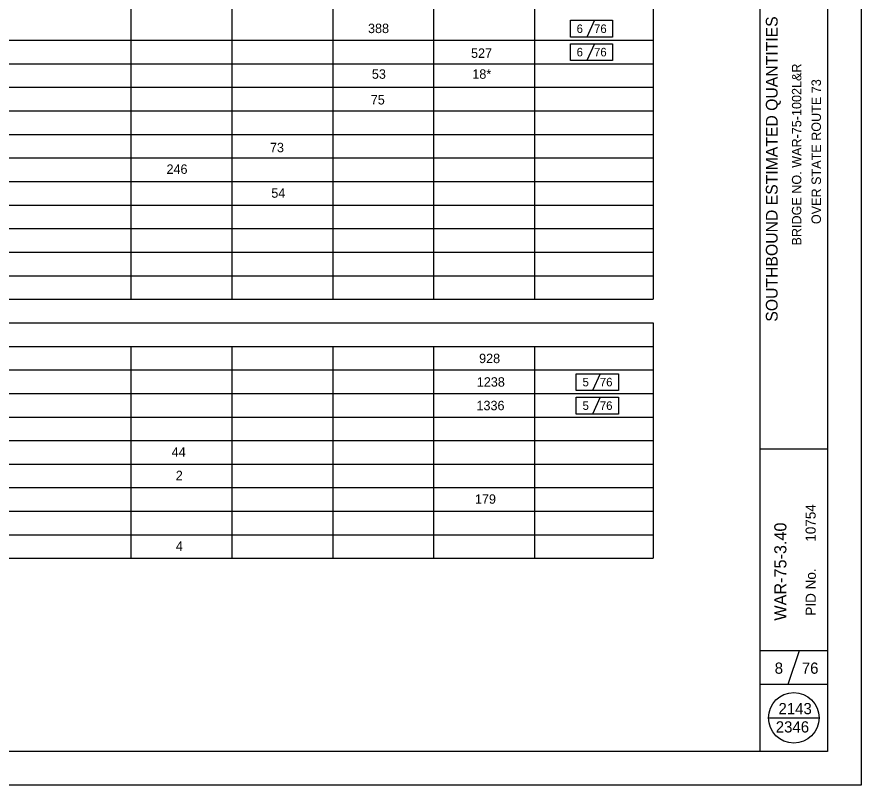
# Model space of a CAD drawing. Extents: x 0 to 34, y 0 to 22.
# Drawn here: x 21.46 to 34, y 0 to 11.42 of the extents above; entities that cross this region are included whole.
import ezdxf

# ---------------------------------------------------------------- set-up
doc = ezdxf.new("R2010")
doc.units = 0
for name, color, linetype in [('BR_P_Gen_Text', 7, 'Continuous'), ('BR_P_Sub_Text', 7, 'Continuous'), ('SH_Border', 7, 'Continuous'), ('SH_Cut_Line', 7, 'Continuous'), ('SH_Data', 7, 'Continuous'), ('SH_Text', 7, 'Continuous')]:
    doc.layers.add(name, color=color, linetype=linetype)

msp = doc.modelspace()

# ---------------------------------------------------------------- linework, layer by layer
at = {"layer": 'BR_P_Gen_Text'}
for p, q in [((30.038, 11.367), (29.923, 11.117)), ((30.038, 11.019), (29.923, 10.769)), ((30.125, 6.115), (30.009, 5.865)), ((30.125, 5.765), (30.009, 5.515))]:
    msp.add_line(p, q, dxfattribs=at)
for points in [[(29.681, 11.367), (30.307, 11.367), (30.307, 11.117), (29.681, 11.117)], [(29.681, 11.367), (30.307, 11.367), (30.307, 11.117), (29.681, 11.117)], [(29.681, 11.019), (30.307, 11.019), (30.307, 10.769), (29.681, 10.769)], [(29.681, 11.019), (30.307, 11.019), (30.307, 10.769), (29.681, 10.769)], [(29.768, 6.115), (30.394, 6.115), (30.394, 5.865), (29.768, 5.865)], [(29.768, 6.115), (30.394, 6.115), (30.394, 5.865), (29.768, 5.865)], [(29.768, 5.765), (30.394, 5.765), (30.394, 5.515), (29.768, 5.515)], [(29.768, 5.765), (30.394, 5.765), (30.394, 5.515), (29.768, 5.515)]]:
    msp.add_lwpolyline(points, close=True, dxfattribs=at)
at = {"layer": 'SH_Border'}
for p, q in [((32.5, 0.5), (32.5, 21.5)), ((32.5, 0.5), (32.5, 21.5)), ((32.5, 0.5), (32.5, 21.5)), ((32.5, 5), (33.5, 5)), ((32.5, 5), (33.5, 5)), ((32.5, 5), (33.5, 5)), ((32.5, 2), (33.5, 2)), ((32.917, 1.5), (33.083, 2)), ((32.5, 1.5), (33.5, 1.5))]:
    msp.add_line(p, q, dxfattribs=at)
msp.add_lwpolyline([(2, 21.5), (33.5, 21.5), (33.5, 0.5), (2, 0.5)], close=True, dxfattribs=at)
at = {"layer": 'SH_Cut_Line'}
msp.add_lwpolyline([(0, 22), (34, 22), (34, 0), (0, 0)], close=True, dxfattribs=at)
at = {"layer": 'SH_Data'}
msp.add_line((32.625, 1), (33.375, 1), dxfattribs=at)
msp.add_line((32.625, 1), (33.375, 1), dxfattribs=at)
msp.add_line((32.625, 1), (33.375, 1), dxfattribs=at)
msp.add_circle((33, 1), 0.375, dxfattribs=at)
at = {"layer": 'SH_Text'}
for p, q in [((30.91, 20.779), (30.91, 7.221)), ((23.15, 19.821), (23.15, 7.221)), ((24.65, 19.821), (24.65, 7.221)), ((26.15, 19.821), (26.15, 7.221)), ((27.65, 19.821), (27.65, 7.221)), ((29.15, 19.821), (29.15, 7.221)), ((3.59, 11.071), (30.91, 11.071)), ((3.59, 10.721), (30.91, 10.721)), ((3.59, 10.721), (30.91, 10.721)), ((3.59, 10.371), (30.91, 10.371)), ((3.59, 10.371), (30.91, 10.371)), ((3.59, 10.021), (30.91, 10.021)), ((3.59, 9.671), (30.91, 9.671)), ((3.59, 9.321), (30.91, 9.321)), ((3.59, 8.971), (30.91, 8.971)), ((3.59, 8.621), (30.91, 8.621)), ((3.59, 8.271), (30.91, 8.271)), ((3.59, 7.921), (30.91, 7.921)), ((3.59, 7.571), (30.91, 7.571)), ((3.59, 7.221), (30.91, 7.221)), ((3.59, 6.871), (30.91, 6.871)), ((3.59, 6.871), (30.91, 6.871)), ((30.91, 6.871), (30.91, 3.371)), ((3.59, 6.521), (30.91, 6.521)), ((23.15, 6.521), (23.15, 3.371)), ((24.65, 6.521), (24.65, 3.371)), ((26.15, 6.521), (26.15, 3.371)), ((27.65, 6.521), (27.65, 3.371)), ((29.15, 6.521), (29.15, 3.371)), ((3.59, 6.171), (30.91, 6.171)), ((3.59, 5.821), (30.91, 5.821)), ((3.59, 5.471), (30.91, 5.471)), ((3.59, 5.121), (30.91, 5.121)), ((3.59, 4.771), (30.91, 4.771)), ((3.59, 4.421), (30.91, 4.421)), ((3.59, 4.071), (30.91, 4.071)), ((3.59, 3.721), (30.91, 3.721)), ((3.59, 3.371), (30.91, 3.371))]:
    msp.add_line(p, q, dxfattribs=at)

# ---------------------------------------------------------------- texts
at = {"layer": 'BR_P_Gen_Text'}
for s, height, p in [('6', 0.126, (29.774, 11.179)), ('76', 0.1259, (30.033, 11.179)), ('6', 0.126, (29.774, 10.831)), ('76', 0.1259, (30.033, 10.831)), (' 5', 0.1259, (29.815, 5.927)), ('76', 0.1259, (30.119, 5.927)), (' 5', 0.1259, (29.815, 5.577)), ('76', 0.1259, (30.119, 5.577))]:
    msp.add_text(s, height=height, dxfattribs=at).set_placement(p)
at = {"layer": 'BR_P_Sub_Text'}
msp.add_text('WAR-75-3.40', height=0.18, rotation=90, dxfattribs=at).set_placement((32.89, 2.444))
at = {"layer": 'SH_Data'}
for s, height, p in [('     SOUTHBOUND ESTIMATED QUANTITIES    ', 0.175, (32.76, 6.563)), ('BRIDGE NO. WAR-75-1002L&R', 0.14, (33.112, 8.02)), ('OVER STATE ROUTE 73', 0.14, (33.403, 8.338)), ('10754', 0.15, (33.325, 3.618)), ('PID No.', 0.15, (33.327, 2.519))]:
    msp.add_text(s, height=height, rotation=90, dxfattribs=at).set_placement(p)
for s, height, p in [('8', 0.167, (32.716, 1.655)), ('76', 0.1666, (33.119, 1.655)), ('2143', 0.1666, (32.772, 1.054)), ('2346', 0.1666, (32.732, 0.782))]:
    msp.add_text(s, height=height, dxfattribs=at).set_placement(p)
at = {"layer": 'SH_Text'}
for s, p in [('388', (26.675, 11.177)), ('527', (28.205, 10.809)), ('53', (26.732, 10.498)), ('18*', (28.224, 10.498)), ('75', (26.716, 10.116)), ('73', (25.218, 9.406)), ('246', (23.681, 9.085)), ('54', (25.238, 8.73)), ('928', (28.325, 6.272)), ('1238', (28.291, 5.922)), ('1336', (28.286, 5.572)), ('44', (23.759, 4.882)), ('2', (23.819, 4.532)), ('179', (28.263, 4.182)), ('4', (23.82, 3.482))]:
    msp.add_text(s, height=0.14, dxfattribs=at).set_placement(p)

doc.saveas('drawing.dxf')
